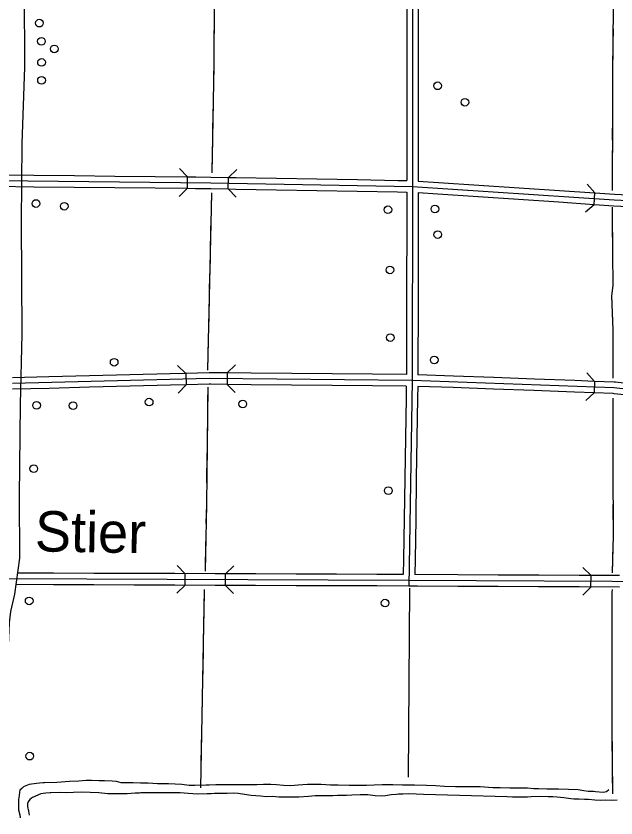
# Model space of a CAD drawing. Extents: x -4306 to 3843, y 131 to 8053.
# Drawn here: x -251 to 1003, y 190 to 1865 of the extents above; entities that cross this region are included whole.
import ezdxf

# ---------------------------------------------------------------- set-up
doc = ezdxf.new("R2010")
doc.units = 0
for name, color, linetype in [('10', 7, 'Continuous'), ('24', 7, 'Continuous'), ('32', 7, 'Continuous'), ('38', 7, 'Continuous'), ('43', 7, 'Continuous'), ('5', 7, 'Continuous'), ('56', 7, 'Continuous')]:
    doc.layers.add(name, color=color, linetype=linetype)

msp = doc.modelspace()

# ---------------------------------------------------------------- linework, layer by layer
at = {"layer": '10'}
msp.add_lwpolyline([(-229.9, 2753.2), (-230.3, 2716.3), (-231, 2305.2), (-234.2, 1917.5), (-233.4, 1758), (-238.7, 1599), (-240.3, 1434.8), (-238.9, 1200.9), (-242.2, 1053.5), (-244.1, 861.8), (-243.5, 732.4), (-254.4, 657.4), (-262.5, 621.4), (-265.5, 597.6), (-272.4, 440.2), (-274.5, 304.9), (-274.4, 293.9)], dxfattribs=at)
at = {"layer": '32'}
for p, q in [((577.4, 1912.9), (577.5, 1509.2)), ((565.4, 1901.4), (565.4, 1828.4)), ((589.4, 1900.3), (589.4, 1828.4)), ((565.4, 1828.4), (565.4, 1743.9)), ((589.4, 1828.4), (589.4, 1743.9)), ((565.4, 1743.9), (565.5, 1659.4)), ((589.4, 1743.9), (589.5, 1659.5)), ((565.5, 1659.4), (565.5, 1575)), ((589.5, 1659.5), (589.5, 1575)), ((565.5, 1575), (565.5, 1521.4)), ((589.5, 1575), (589.5, 1520.4)), ((-1096.1, 1530.1), (156, 1516.7)), ((-298, 1533.5), (-213.6, 1532.6)), ((-213.6, 1532.6), (-129.1, 1531.7)), ((-129.1, 1531.7), (-44.6, 1530.8)), ((-44.6, 1530.8), (39.9, 1529.9)), ((39.9, 1529.9), (107.4, 1529.2)), ((107.2, 1505.2), (107.4, 1529.2)), ((107.4, 1529.2), (124.4, 1529)), ((124.4, 1529), (156.1, 1528.7)), ((156.1, 1528.7), (192.9, 1528)), ((192.5, 1504), (193, 1528)), ((192.9, 1528), (208.9, 1527.7)), ((208.9, 1527.7), (293.4, 1526.3)), ((293.4, 1526.3), (377.9, 1524.8)), ((377.9, 1524.8), (462.4, 1523.3)), ((-298.3, 1509.5), (-213.8, 1508.6)), ((-213.8, 1508.6), (-129.3, 1507.7)), ((-129.3, 1507.7), (-44.8, 1506.8)), ((156, 1516.7), (577.5, 1509.2)), ((462.4, 1523.3), (546.8, 1521.8)), ((546.8, 1521.8), (565.5, 1521.4)), ((577.5, 1509.2), (576.7, 1103.9)), ((577.5, 1509.2), (999.1, 1480.9)), ((589.5, 1520.4), (631.8, 1517.6)), ((631.8, 1517.6), (716.1, 1511.9)), ((716.1, 1511.9), (800.4, 1506.3)), ((-44.8, 1506.8), (39.6, 1505.9)), ((39.6, 1505.9), (107.2, 1505.2)), ((107.2, 1505.2), (124.1, 1505)), ((124.1, 1505), (155.8, 1504.7)), ((155.8, 1504.7), (192.5, 1504)), ((192.5, 1504), (208.5, 1503.7)), ((208.5, 1503.7), (293, 1502.3)), ((293, 1502.3), (377.5, 1500.8)), ((377.5, 1500.8), (461.9, 1499.3)), ((461.9, 1499.3), (546.4, 1497.8)), ((546.4, 1497.8), (565.5, 1497.4)), ((565.5, 1497.4), (565.3, 1406)), ((589.5, 1496.4), (589.3, 1406)), ((589.5, 1496.4), (630.2, 1493.7)), ((630.2, 1493.7), (714.5, 1488)), ((800.4, 1506.3), (884.7, 1500.6)), ((884.7, 1500.6), (958.4, 1495.7)), ((956.8, 1471.7), (958.4, 1495.7)), ((958.4, 1495.7), (969, 1495)), ((969, 1495), (999.8, 1492.9)), ((999.8, 1492.9), (1044.4, 1490.7)), ((714.5, 1488), (798.8, 1482.3)), ((798.8, 1482.3), (883.1, 1476.7)), ((883.1, 1476.7), (956.6, 1471.7)), ((999.1, 1480.9), (1414, 1460.6)), ((956.8, 1471.7), (967.4, 1471)), ((967.4, 1471), (998.4, 1468.9)), ((998.4, 1468.9), (1043.2, 1466.7)), ((565.3, 1406), (565.1, 1321.5)), ((589.3, 1406), (589.1, 1321.5)), ((565.1, 1321.5), (565, 1237)), ((589.1, 1321.5), (589, 1237)), ((565, 1237), (564.8, 1152.5)), ((589, 1237), (588.8, 1152.5)), ((564.8, 1152.5), (564.7, 1116)), ((588.8, 1152.5), (588.7, 1115.5)), ((-182.2, 1111.3), (-258.4, 1109.3)), ((152.6, 1107.8), (-258.3, 1097.3)), ((-97.7, 1113.4), (-182.2, 1111.3)), ((-13.3, 1115.6), (-97.7, 1113.4)), ((71.2, 1117.8), (-13.3, 1115.6)), ((104, 1118.6), (71.2, 1117.8)), ((152.5, 1119.8), (104, 1118.6)), ((104, 1118.6), (104.6, 1094.6)), ((156.1, 1119.8), (152.5, 1119.8)), ((576.7, 1103.9), (152.6, 1107.8)), ((190.2, 1119.5), (156.1, 1119.8)), ((190.2, 1119.5), (189.9, 1095.5)), ((240.6, 1119), (190.2, 1119.5)), ((325, 1118.2), (240.6, 1119)), ((409.5, 1117.5), (325, 1118.2)), ((494, 1116.7), (409.5, 1117.5)), ((564.7, 1116), (494, 1116.7)), ((663.3, 1112.8), (588.7, 1115.5)), ((747.7, 1109.7), (663.3, 1112.8)), ((832.1, 1106.5), (747.7, 1109.7)), ((916.6, 1103.4), (832.1, 1106.5)), ((-97.1, 1089.5), (-181.6, 1087.3)), ((-12.7, 1091.6), (-97.1, 1089.5)), ((71.8, 1093.8), (-12.7, 1091.6)), ((104.6, 1094.6), (71.8, 1093.8)), ((152.7, 1095.8), (104.6, 1094.6)), ((155.9, 1095.8), (152.7, 1095.8)), ((189.9, 1095.5), (155.9, 1095.8)), ((240.3, 1095), (189.9, 1095.5)), ((324.8, 1094.2), (240.3, 1095)), ((409.3, 1093.5), (324.8, 1094.2)), ((493.8, 1092.7), (409.3, 1093.5)), ((564.5, 1092), (493.8, 1092.7)), ((564.5, 1092), (564.1, 1068.2)), ((576.7, 1103.9), (569.9, 674.2)), ((997.9, 1088.4), (576.7, 1103.9)), ((588.5, 1091.5), (588.1, 1067.8)), ((662.4, 1088.8), (588.5, 1091.5)), ((957.9, 1101.9), (916.6, 1103.4)), ((958, 1101.9), (957.2, 1077.9)), ((998.8, 1100.4), (957.9, 1101.9)), ((1001.9, 1100.1), (998.8, 1100.4)), ((1043.5, 1095.5), (1001.9, 1100.1)), ((-181.6, 1087.3), (-258.2, 1085.3)), ((746.8, 1085.7), (662.4, 1088.8)), ((831.2, 1082.6), (746.8, 1085.7)), ((915.7, 1079.5), (831.2, 1082.6)), ((957.2, 1077.9), (915.7, 1079.5)), ((997.1, 1076.5), (957.2, 1077.9)), ((999.2, 1076.2), (997.1, 1076.5)), ((1168.5, 1069.5), (997.9, 1088.4)), ((1040.8, 1071.6), (999.2, 1076.2)), ((564.1, 1068.2), (562.8, 983.7)), ((588.1, 1067.8), (586.8, 983.4)), ((562.8, 983.7), (561.4, 899.3)), ((586.8, 983.4), (585.4, 898.9)), ((561.4, 899.3), (560.1, 814.8)), ((585.4, 898.9), (584.1, 814.4)), ((560.1, 814.8), (558.8, 730.3)), ((584.1, 814.4), (582.8, 729.9)), ((558.8, 730.3), (558.3, 698.2)), ((582.8, 729.9), (582.3, 698.1)), ((-172.7, 701.2), (-248, 701.5)), ((-88.2, 700.8), (-172.7, 701.2)), ((-3.7, 700.5), (-88.2, 700.8)), ((80.8, 700.2), (-3.7, 700.5)), ((165.3, 699.8), (80.8, 700.2)), ((102.2, 676.1), (102.3, 700.1)), ((249.8, 699.5), (165.3, 699.8)), ((186.8, 675.7), (186.9, 699.7)), ((334.2, 699.1), (249.8, 699.5)), ((418.7, 698.8), (334.2, 699.1)), ((503.2, 698.5), (418.7, 698.8)), ((558.3, 698.2), (503.2, 698.5)), ((672.2, 697.7), (582.3, 698.1)), ((756.7, 697.3), (672.2, 697.7)), ((841.2, 696.9), (756.7, 697.3)), ((925.7, 696.5), (841.2, 696.9)), ((1010.2, 696.1), (925.7, 696.5)), ((950.4, 672.3), (950.5, 696.4)), ((-172.8, 677.2), (-251.5, 677.5)), ((-88.3, 676.8), (-172.8, 677.2)), ((-3.8, 676.5), (-88.3, 676.8)), ((80.7, 676.2), (-3.8, 676.5)), ((165.2, 675.8), (80.7, 676.2)), ((249.7, 675.5), (165.2, 675.8)), ((334.1, 675.1), (249.7, 675.5)), ((418.6, 674.8), (334.1, 675.1)), ((503.1, 674.5), (418.6, 674.8)), ((569.9, 674.2), (503.1, 674.5)), ((587.6, 674.1), (569.9, 674.2)), ((672.1, 673.7), (587.6, 674.1)), ((756.6, 673.3), (672.1, 673.7)), ((841.1, 672.9), (756.6, 673.3)), ((925.6, 672.5), (841.1, 672.9)), ((1010, 672.1), (925.6, 672.5))]:
    msp.add_line(p, q, dxfattribs=at)
msp.add_lwpolyline([(2052.2, 1131.5), (2052.1, 731.6), (2051.2, 728.2), (2048.7, 726.1), (1900.1, 653.4), (1410.3, 639.5), (1370.3, 641.2), (1252.7, 662.8), (1223, 668.4), (1168.4, 681.6), (1136.3, 683.4), (569.9, 686.2), (-271.6, 689.6)], dxfattribs=at)
at = {"layer": '38'}
for p, q in [((107.3, 1517.2), (107.3, 1517.2)), ((192.7, 1516), (192.7, 1516)), ((957.6, 1483.7), (957.6, 1483.7))]:
    msp.add_line(p, q, dxfattribs=at)
for points in [[(107.4, 1529.2), (90.7, 1546.4)], [(210.2, 1544.7), (193, 1528)], [(958.4, 1495.7), (942.6, 1513.7)], [(90, 1488.4), (107.2, 1505.2)], [(192.5, 1504), (209.2, 1486.8)], [(938.7, 1455.9), (956.8, 1471.7)], [(86.6, 1135.1), (104, 1118.6)], [(190.2, 1119.5), (207.3, 1136.3)], [(941.6, 1119.5), (957.9, 1101.9)], [(104.6, 1094.6), (88.1, 1077.2)], [(206.8, 1078.4), (189.9, 1095.5)], [(957, 1077.9), (939.4, 1061.6)], [(85.4, 717.1), (102.3, 700.1)], [(186.9, 699.7), (203.9, 716.6)], [(933.7, 713.4), (950.5, 696.4)], [(102.2, 676.1), (85.2, 659.2)], [(203.7, 658.7), (186.8, 675.7)], [(950.4, 672.3), (933.4, 655.5)]]:
    msp.add_lwpolyline(points, dxfattribs=at)
at = {"layer": '43'}
for points in [[(999.3, 2313.2), (999.2, 2286.4), (997.2, 2101.7), (996.6, 2003.3), (996.9, 1879.7), (995.5, 1749.8), (995.1, 1656.3), (994.6, 1501.8), (994.6, 1500.8)], [(163.4, 1912.9), (163.3, 1899.3), (162.2, 1772.3), (161.1, 1685.1), (157.9, 1537.8)], [(162.9, 1860.1), (162.4, 1796.7)], [(996.5, 1838), (996.1, 1806.3)], [(996.1, 1806.3), (995.8, 1774.6)], [(162.2, 1775.6), (162.2, 1772.3), (161.5, 1712.2)], [(995.5, 1753.5), (995.5, 1749.8), (995.3, 1690.1)], [(161.2, 1691.1), (161.1, 1685.1), (159.9, 1627.7)], [(995.2, 1669), (995.1, 1656.3), (995, 1605.6)], [(159.4, 1606.6), (158, 1543.3)], [(994.9, 1584.5), (994.7, 1521.1)], [(157.2, 1495.8), (156.8, 1462.7), (149, 1125.3)], [(157.2, 1495.8), (156.8, 1464.1)], [(994.7, 1466), (994.9, 1435.7), (996.1, 1302.2), (993.6, 1280.5), (995.8, 1209.4), (996.2, 1108.8)], [(994.7, 1466), (994.9, 1435.7), (994.9, 1434.3)], [(156.3, 1443), (154.8, 1379.6)], [(995.1, 1413.2), (995.6, 1349.8)], [(154.4, 1358.5), (152.9, 1295.2)], [(995.8, 1328.7), (996.1, 1302.2), (993.6, 1280.5), (994.1, 1265.5)], [(152.4, 1274), (151, 1210.7)], [(994.7, 1244.4), (995.8, 1209.4), (995.9, 1181)], [(150.5, 1189.6), (149, 1126.2)], [(996, 1159.9), (996.2, 1108.8)], [(149.7, 1089.9), (146.7, 844.5), (144, 705.7)], [(149.7, 1089.9), (149.3, 1058.2)], [(996.3, 1066.8), (996.1, 928.4), (996.5, 780.1), (995, 701.7)], [(996.3, 1066.8), (996.2, 1035.1)], [(149.1, 1037.1), (148.3, 973.7)], [(996.2, 1014), (996.1, 950.6)], [(148, 952.6), (147.2, 889.2)], [(996.1, 929.5), (996.1, 928.4), (996.3, 866.1)], [(147, 868.1), (146.7, 844.5), (145.9, 804.8)], [(996.3, 845), (996.5, 781.6)], [(145.5, 783.6), (144.2, 720.3)], [(996.2, 760.5), (995, 701.7)], [(135, 252.6), (143.2, 666.8)], [(142.7, 643.3), (143.2, 666.8)], [(994.4, 666.9), (994.3, 661.5), (994.1, 386.3), (995.2, 240.6)], [(994.4, 666.9), (994.3, 661.5), (994.3, 635.2)], [(141.1, 558.8), (142.3, 622.2)], [(994.2, 614.1), (994.2, 550.7)], [(139.4, 474.4), (140.6, 537.7)], [(994.2, 529.6), (994.2, 466.2)], [(137.7, 389.9), (139, 453.2)], [(994.2, 445.1), (994.1, 386.3), (994.2, 381.8)], [(136.1, 305.4), (137.3, 368.8)], [(994.3, 360.6), (994.8, 297.3)], [(123, 257.9), (110.7, 258), (95.2, 259.6), (81.9, 260.3), (67.7, 261.1), (44.6, 261.4), (25, 262.3), (9.3, 262.7), (-6.5, 263.2), (-31.6, 263.4), (-41.1, 265.8), (-50.2, 266.8), (-65.9, 267.2), (-77.9, 267.3), (-93.5, 268.1), (-104.4, 267.8), (-119.9, 266.8), (-139.3, 265.8), (-166, 264.2), (-191.3, 263.2)], [(994.9, 276.1), (995.1, 248.3)], [(-191.3, 263.2), (-194.5, 263.1), (-201.8, 262.4), (-208.2, 261.8), (-223.4, 260.1), (-234.1, 255.5), (-235.2, 254.7), (-239.1, 251.6), (-242.7, 247.7), (-244, 243.7), (-244.3, 236.9), (-245.8, 228.4), (-245.5, 219.8), (-245.7, 206.7), (-243, 196.7), (-242.3, 189.9)], [(224.3, 259.2), (212.7, 259.4), (202.6, 258.9), (187.7, 258.8), (166.5, 258.8), (152.6, 258.4), (146.6, 258.6), (123, 257.9)], [(988, 248.3), (982.9, 244.7), (976.2, 243.2), (959.7, 244.6), (955.9, 244.8), (944.2, 245.4), (935.7, 246.5), (923.4, 248.4), (903.4, 249.3), (882.3, 250.1), (869.8, 249.9), (858, 250.2), (840.6, 250.8), (830.8, 250.9), (818, 251.8), (800, 252.3), (780.6, 252.4), (760.9, 252.5), (745, 253.1), (718.7, 254.8), (701.1, 254.6), (684.8, 255.1), (667.6, 254.9), (644.4, 255.9), (625.7, 257.3), (607, 257.8), (581.4, 258.3), (556.4, 258.3), (536.4, 259.2), (514.4, 259.3), (497.6, 258.1), (481.3, 257.6), (462.9, 257.9), (445.2, 258), (422, 258.1), (406.3, 258.6), (386.6, 259.6), (371.1, 260.1), (358, 259.6), (338.5, 258.1), (323.5, 257.2), (307.7, 258), (293.3, 259.2), (281.4, 259.5), (266.4, 260.1), (252, 259.2), (237.5, 259), (224.3, 259.2)], [(-188.4, 241.6), (-194.4, 241.1), (-199.2, 240.3), (-216.4, 232.8), (-218.7, 231.3), (-221.9, 228.2), (-225.5, 223.6), (-227, 220.2), (-227.1, 213.5), (-225, 204.2), (-223.8, 195.7)], [(285.7, 234.5), (271.9, 234.3), (259.9, 235.3), (240.2, 236.8), (226.2, 239.2), (213.2, 240.9), (204.1, 241.4), (190.2, 241), (171.5, 240.8), (164, 240.8), (157.1, 240.6), (148.5, 240.6), (128, 239.6), (108.6, 240.8), (92.3, 242.3), (68.5, 242.2), (47.6, 242.1), (30.3, 242.1), (9.8, 242.1), (7.3, 241.9), (-2, 241.5), (-18.9, 240.4), (-34, 240.5), (-59.2, 240.4), (-77.8, 242.6), (-96.2, 242.9), (-114.9, 243.7), (-130.7, 243), (-146.1, 242.5), (-159.2, 243.1), (-178.5, 242.6), (-179.6, 242.5), (-188.4, 241.6)], [(1005.2, 226.9), (993.7, 226.4), (981.5, 226.7), (971.1, 226.4), (958.5, 227.2), (945.5, 228.2), (937.1, 228.4), (926, 229.2), (914.3, 229.3), (908.4, 229.9), (893.9, 231.8), (879.6, 233.2), (870.5, 233.7), (860.9, 234), (841.9, 234.7), (825.3, 234.1), (817.6, 233.1), (810.6, 233.2), (801.9, 233.2), (786.6, 233.6), (775.2, 233.9), (675.8, 236.7), (600.8, 239), (570.1, 240), (557.4, 239.8), (547.9, 239.6), (543.9, 239.2), (532.7, 238), (521.3, 236.2), (512.1, 235.4), (499.6, 236), (484.2, 238.1), (468.2, 238.5), (450.7, 237.7), (439.6, 237.1), (430, 237.1), (421.1, 236.9), (411.3, 236.4), (400.3, 236.4), (383.3, 236), (374.1, 236), (360.3, 234.9), (339.7, 233.5), (322.8, 233), (311.7, 233.3), (298.5, 233.4), (285.7, 234.5)]]:
    msp.add_lwpolyline(points, dxfattribs=at)
at = {"layer": '5'}
msp.add_line((570.9, 670.2), (568.3, 275.2), dxfattribs=at)
at = {"layer": '56'}
for centre in [(-202, 1850.2), (-197.9, 1812.3), (-170.9, 1796.4), (-197.7, 1768.1), (-197.7, 1730.8), (629.9, 1719.3), (687, 1685), (-209.4, 1473.4), (-150.2, 1467.8), (526, 1460.3), (624.4, 1461.9), (630.3, 1408.6), (530.3, 1334.7), (531, 1193.4), (-45.9, 1141.8), (623, 1146.6), (-208.1, 1051.8), (-131.7, 1051.2), (27.2, 1058.6), (222.8, 1054.7), (-213.9, 919.5), (527, 873.6), (-223.5, 643.3), (520.2, 638.7), (-222.3, 319)]:
    msp.add_circle(centre, 8, dxfattribs=at)

# ---------------------------------------------------------------- texts
at = {"layer": '24'}
msp.add_text('Stier', height=84.49, rotation=358.9554, dxfattribs=at).set_placement((-212, 746.9))

doc.saveas('drawing.dxf')
